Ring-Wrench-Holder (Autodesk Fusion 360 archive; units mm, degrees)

design "Ring-Wrench-Holder" references "Base"
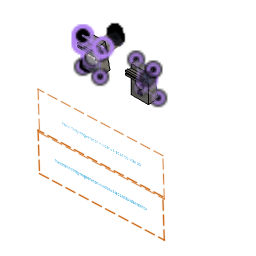
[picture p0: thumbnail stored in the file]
parameter "stick_diameter" = 24
parameter "stick_length" = 34
parameter "angle" = 10
parameter "calculated_height" = 34 (= "stick_diameter + 10 mm")
parameter "screw_tolerance" = 0.3
parameter "screw_dept" = 4
parameter "screw_hole_diameter" = 6
component_insert "Component Insert"
work_plane "WorkPlane1" AlongDistance 55.612
sketch "Sketch1" plane through (0, 55.6118, 0) normal (0, 1, 0) x axis (1, 0, 0)
  line L1 (40, -60) -> (0, -60)
sketch "Sketch2" plane through (0, 0, 0) normal (1, 0, 0) x axis (0, 1, 0)
  line L1 (65.4599, 61.7365) -> (55.6118, 60)
  line L2 (65.6118, 60) -> (55.6118, 60)
  line L3 (64.9888, 6.8204) -> (55.6118, 60)
  line L4 (74.8369, 8.5569) -> (65.4599, 61.7365)
  line L5 (64.9888, 6.8204) -> (74.8369, 8.5569)
  point P2 (55.6118, 60)
  point P3 (55.6118, 60)
  point P6 (55.6118, 60)
  point P4 (65.4599, 61.7365)
  point P7 (64.9888, 6.8204)
  horizontal L2
  coincident P2 P3
  coincident P2 P6
  perpendicular L1 L3
  perpendicular L1 L4
  equal L3 L4
  dimension "d6" distance P3 P4 = 10
  dimension "d7" angle L1 L2 = 10 (= "angle")
  dimension "d9" distance P6 P7 = 54 (= "calculated_height + 20 mm")
extrude "Extrude1" new body sketch "Sketch2" profile of L1 L3 L4 L5 along normal blind 34 (= "calculated_height") bodies "Holder"
sketch "Sketch3" plane through (0, 0, 0) normal (-1, 0, 0) x axis (0, -1, 0)
  line L1 (-55.6118, 60) -> (-64.9888, 6.8204)
  line L2 (-65.4599, 61.7365) -> (-55.6118, 60)
  line L3 (-74.8369, 8.5569) -> (-65.4599, 61.7365)
  line L4 (-64.9888, 6.8204) -> (-74.8369, 8.5569)
  line L5 (-55.6118, 6.8204) -> (-55.6118, 60)
  line L6 (-64.9888, 6.8204) -> (-55.6118, 6.8204)
  point P3 (-55.6118, 60)
  point P8 (-55.6118, 60)
  point P7 (-64.9888, 6.8204)
  point P10 (-64.9888, 6.8204)
  coincident P3 P8
  vertical L5
  coincident P7 P10
  perpendicular L5 L6
extrude "Extrude2" add sketch "Sketch3" profile of L1 L5 L6 to an object
sketch "Sketch4" plane through (0, 74.0436, 13.0559) normal (0, 0.9848, 0.1736) x axis (-1, 0, 0)
  line L1 (0, 49.4316) -> (0, -4.5684)
  line L2 (-34, 49.4316) -> (0, 49.4316)
  line L3 (-34, -4.5684) -> (-34, 49.4316)
  line L4 (0, -4.5684) -> (-34, -4.5684)
  line L5 (0, -4.5684) -> (-34, 49.4316)
  circle C1 centre (-17, 22.4316) radius 12
  point P4 (-34, 49.4316)
  point P6 (-34, 49.4316)
  point P2 (0, -4.5684)
  point P7 (0, -4.5684)
  point P8 (-17, 22.4316)
  coincident P4 P6
  coincident P2 P7
  midpoint L5 P8
  dimension "d14" diameter C1 = 24 (= "stick_diameter")
extrude "Extrude3" new body sketch "Sketch4" profile of C1 along normal blind 34 (= "stick_length") bodies "Stick"
sketch "Sketch5" plane through (0, 107.5271, 18.9599) normal (0, 0.9848, 0.1736) x axis (-1, 0, 0)
  line L1 (-17, 34.4316) -> (-17, 22.4316)
  line L2 (-22.9375, 22.1004) -> (-20.2555, 27.408)
  line L3 (-19.6819, 17.124) -> (-22.9375, 22.1004)
  line L4 (-13.7445, 17.4551) -> (-19.6819, 17.124)
  line L5 (-11.0625, 22.7627) -> (-13.7445, 17.4551)
  line L6 (-14.3181, 27.7392) -> (-11.0625, 22.7627)
  line L7 (-20.2555, 27.408) -> (-14.3181, 27.7392)
  circle C1 centre (-17, 22.4316) radius 12
  circle C2 centre (-17, 22.4316) radius 3.15
  point P2 (-17, 22.4316)
  point P3 (-17, 22.4316)
  point P4 (-17, 34.4316)
  point P11 (-17, 22.4316)
  point P12 (-17, 22.4316)
  coincident P2 P3
  coincident C1 P4
  vertical L1
  coincident P2 P11
  coincident P3 P12
  dimension "d17" distance P11 L7 = 5.15 (= "5 mm + ( screw_tolerance / 2 )")
  dimension "d23" diameter C2 = 6.3 (= "screw_hole_diameter + screw_tolerance")
extrude "Extrude4" cut sketch "Sketch5" profile of L2 L3 L4 L5 L6 L7 along a picked direction blind -4
extrude "Extrude5" cut sketch "Sketch5" profile of C2 along a picked direction blind -84 (= "-stick_length - 50 mm")
work_plane "WorkPlane2" sketch "Sketch5" AlongDistance 60
sketch "Sketch6" plane through (0, 64.1955, 11.3194) normal (0, 0.9848, 0.1736) x axis (-1, 0, 0)
  line L1 (-19.6819, 17.124) -> (-22.9375, 22.1004)
  line L2 (-13.7445, 17.4551) -> (-19.6819, 17.124)
  line L3 (-11.0625, 22.7627) -> (-13.7445, 17.4551)
  line L4 (-14.3181, 27.7392) -> (-11.0625, 22.7627)
  line L5 (-22.9375, 22.1004) -> (-20.2555, 27.408)
  line L6 (-20.2555, 27.408) -> (-14.3181, 27.7392)
  circle C1 centre (-17, 22.4316) radius 12
  circle C2 centre (-17, 22.4316) radius 5.9467
  circle C3 centre (-17, 22.4316) radius 7.9467
  point P6 (-14.3181, 27.7392)
  concentric C1 C2
  coincident P6 C2
  dimension "d45" = 2
extrude "Extrude6" cut sketch "Sketch6" profile of L1 L2 L3 L4 L5 L6 C3 against normal blind 29
extrude "Extrude7" new body of existing geometry blind 37
extrude "Extrude8" add of existing geometry to an object
extrude "Extrude9" cut of existing geometry to an object
sketch "Text" plane through (0, 55.6118, 0) normal (0, -1, 0) x axis (1, 0, 0)
  line L1 (20.1325, 31.916) -> (0, 31.916)
  curve K1
  curve K2
  curve K3
  curve K4
  line L2 (0, 47.1259) -> (34, 47.1259)
  line L3 (0, 6.8204) -> (0, 47.1259)
  line L4 (34, 6.8204) -> (0, 6.8204)
  line L5 (34, 47.1259) -> (34, 6.8204)
  closed curve K5 centre (17, 32.5835)
  point P2 (0, 31.916)
  point P7 (34, 6.8204)
  coincident P2
  equal K1 L4
  coincident P7
  coincident L4
  dimension "d35" Text1-Height = 2
sketch "Filename" plane through (0, 0, 0) normal (0, 1, 0) x axis (1, 0, 0)
  dimension "d36" = 5
  dimension "d41" = 5
  dimension "d42" = 5
extrude "Extrude10" cut sketch "Text" against normal blind 2
copy_paste_bodies "CopyPasteBodies1"
move "Move1"
sketch "Sketch9" plane through (0, 74.0436, 13.0559) normal (0, 0.9848, 0.1736) x axis (-1, 0, 0)
  line L1 (-95, 49.4316) -> (-95, -4.5684)
  line L2 (-129, 49.4316) -> (-95, 49.4316)
  line L3 (-129, -4.5684) -> (-129, 49.4316)
  line L4 (-95, -4.5684) -> (-129, -4.5684)
  line L5 (-112, -4.5684) -> (-112, 49.4316)
  line L6 (-117.9415, 22.1826) -> (-115.1864, 27.4526)
  line L7 (-114.7551, 17.1616) -> (-117.9415, 22.1826)
  line L8 (-108.8136, 17.4106) -> (-114.7551, 17.1616)
  line L9 (-106.0585, 22.6806) -> (-108.8136, 17.4106)
  line L10 (-109.2449, 27.7016) -> (-106.0585, 22.6806)
  line L11 (-115.1864, 27.4526) -> (-109.2449, 27.7016)
  circle C1 centre (-112, 22.4316) radius 3.15
  circle C2 centre (-112, 22.4316) radius 3.15
  point P8 (-112, 49.4316)
  point P9 (-112, -4.5684)
  point P2 (-112, 22.4316)
  point P16 (-112, 22.4316)
  midpoint L2 P8
  midpoint L4 P9
  coincident P2 P16
  dimension "d44" distance P16 L11 = 5.15 (= "5 mm + ( screw_tolerance / 2 )")
extrude "Extrude11" cut sketch "Sketch9" profile of C1 C2 no distance stored
combine "Combine1" bodies "Holder"
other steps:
base_feature "Base Feature" bodies "Holder", "No stick"
named bodies: "Holder", "Stick", "No stick"

design "Base"
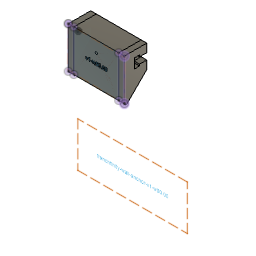
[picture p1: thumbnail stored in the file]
parameter "wall_anchor_height" = 60
parameter "wall_anchor_width" = 20
parameter "wall_anchor_angle" = 45
parameter "width_per_slot" = 40
parameter "slot_inner_width" = 8.5
parameter "slot_inner_height" = 4.5
parameter "slot_outer_width" = 5.6
parameter "slot_outer_height" = 6.5
parameter "slot_dept" = 15
parameter "print_tolerance" = 0.12
parameter "base_plate_thickness" = 16
parameter "base_plate_slot_height" = 50
parameter "wall_anchor_angle_rounded_border" = 1.5
parameter "base_plate_screw_hole_diameter" = 4
parameter "base_plate_screw_head_diameter" = 8
parameter "base_plate_screw_head_height" = 4
parameter "base_plate_screw_hole_side_distance" = 7
parameter "slot_screw_head_width" = 4.42 (= "4.3 mm + print_tolerance")
parameter "slot_screw_thread_width" = 2.12 (= "2 mm + print_tolerance")
parameter "slot_screw_head_height" = 2.12 (= "2 mm + print_tolerance")
parameter "width" = 50
parameter "filament_hole_width" = 1.7
sketch "Side" plane through (0, 0, 0) normal (1, 0, 0) x axis (0, 1, 0)
  line L1 (39.6118, 0) -> (19.6118, 0)
  line L2 (39.6118, 60) -> (39.6118, 0)
  line L3 (19.6118, 60) -> (39.6118, 60)
  line L4 (19.6118, 0) -> (19.6118, 60)
  line L5 (39.6118, 39.6118) -> (0, 0)
  line L6 (56.0196, 0) -> (0, 0)
  point P1 (0, 0)
  point P6 (0, 0)
  point P7 (39.6118, 39.6118)
  point P2 (19.6118, 0)
  point P3 (39.6118, 0)
  point P5 (19.6118, 60)
  horizontal L1
  vertical L2
  horizontal L3
  vertical L4
  horizontal L6
  coincident P1 P6
  coincident L2 P7
  dimension "d4" distance P2 P3 = 20 (= "wall_anchor_width")
  dimension "d5" distance P2 P5 = 60 (= "wall_anchor_height")
  dimension "d6" angle L5 L6 = 45 (= "wall_anchor_angle")
extrude "Extrude1" new body sketch "Side" profile of L1 L2 L3 L4 L5 along normal blind 40 (= "width_per_slot")
sketch "Slot LeftToRight" plane through (0, 0, 0) normal (-1, 0, 0) x axis (0, -1, 0)
  line L1 (-19.6118, 60) -> (-19.6118, 19.6118)
  line L2 (-39.6118, 60) -> (-19.6118, 60)
  line L3 (-39.6118, 39.6118) -> (-39.6118, 60)
  line L4 (-19.6118, 19.6118) -> (-39.6118, 39.6118)
  line L5 (-39.6118, 52.6059) -> (-39.6118, 49.8059)
  line L6 (-39.6118, 47.0059) -> (-39.6118, 49.8059)
  line L7 (-33.1118, 52.6059) -> (-39.6118, 52.6059)
  line L8 (-28.6118, 49.8059) -> (-39.6118, 49.8059)
  line L9 (-28.6118, 54.0559) -> (-28.6118, 49.8059)
  line L10 (-33.1118, 54.0559) -> (-28.6118, 54.0559)
  line L11 (-33.1118, 52.6059) -> (-33.1118, 54.0559)
  line L12 (-28.6118, 45.5559) -> (-28.6118, 49.8059)
  line L13 (-33.1118, 45.5559) -> (-28.6118, 45.5559)
  line L14 (-33.1118, 47.0059) -> (-33.1118, 45.5559)
  line L15 (-33.1118, 47.0059) -> (-39.6118, 47.0059)
  point P6 (-39.6118, 49.8059)
  point P7 (-39.6118, 52.6059)
  point P17 (-39.6118, 47.0059)
  point P9 (-33.1118, 52.6059)
  point P16 (-33.1118, 47.0059)
  point P10 (-28.6118, 49.8059)
  point P13 (-28.6118, 49.8059)
  point P11 (-28.6118, 54.0559)
  point P14 (-28.6118, 45.5559)
  point P12 (-33.1118, 54.0559)
  point P15 (-33.1118, 45.5559)
  midpoint L3 P6
  parallel L3 L5
  parallel L3 L6
  perpendicular L3 L7
  perpendicular L6 L8
  perpendicular L8 L9
  perpendicular L9 L10
  symmetric P7 L8 P17
  symmetric P9 L8 P16
  symmetric P10 L8 P13
  symmetric L8 P11 P14
  symmetric L8 P12 P15
  dimension "d80" distance P6 P7 = 2.8 (= "slot_outer_width / 2")
  dimension "d82" distance P7 P9 = 6.5 (= "slot_outer_height")
  dimension "d84" distance P6 P10 = 11 (= "slot_outer_height + slot_inner_height")
  dimension "d85" distance P10 P11 = 4.25 (= "slot_inner_width / 2")
  dimension "d86" distance P11 P12 = 4.5 (= "slot_inner_height")
extrude "Extrude3" cut sketch "Slot LeftToRight" profile of L3 L5 L6 L7 L9 L10 L11 L12 L13 L14 L15 against normal blind 40 (magnitude of "width_per_slot * -1")
sketch "Plate" plane through (0, 39.6118, 0) normal (0, 1, 0) x axis (-1, 0, 0)
  line L1 (0, 39.6118) -> (-40, 39.6118)
  line L2 (-40, 60) -> (0, 60)
  line L3 (0, 10) -> (0, 60)
  line L4 (-40, 10) -> (-40, 60)
  line L5 (-40, 10) -> (0, 10)
  line L6 (-40, 47.0059) -> (0, 47.0059)
  line L7 (-40, 52.6059) -> (-40, 60)
  line L8 (0, 60) -> (0, 52.6059)
  line L9 (0, 52.6059) -> (-40, 52.6059)
  line L10 (-40, 60) -> (0, 60)
  line L11 (-40, 39.6118) -> (-40, 47.0059)
  line L12 (0, 47.0059) -> (0, 39.6118)
  point P2 (0, 60)
  point P3 (-40, 60)
  point P4 (0, 10)
  point P5 (-40, 10)
  perpendicular L1 L3
  perpendicular L1 L4
  dimension "d36" distance P2 P3 = 40 (= "width_per_slot")
  dimension "d37" distance P2 P4 = 50 (= "base_plate_slot_height")
  dimension "d39" distance P3 P5 = 50 (= "base_plate_slot_height")
extrude "Extrude6" new body sketch "Plate" profile of L1 L2 L3 L4 L5 L6 L7 L8 L9 L10 along normal blind 16 (= "base_plate_thickness") bodies "Base plate with slot"
sketch "Slot" plane through (0, 0, 0) normal (-1, 0, 0) x axis (0, -1, 0)
  line L1 (-19.6118, 60) -> (-19.6118, 19.6118)
  line L2 (-39.6118, 60) -> (-19.6118, 60)
  line L3 (-39.6118, 52.6059) -> (-39.6118, 60)
  line L4 (-33.1118, 52.6059) -> (-39.6118, 52.6059)
  line L5 (-33.1118, 54.0559) -> (-33.1118, 52.6059)
  line L6 (-28.6118, 54.0559) -> (-33.1118, 54.0559)
  line L7 (-28.6118, 45.5559) -> (-28.6118, 54.0559)
  line L8 (-33.1118, 45.5559) -> (-28.6118, 45.5559)
  line L9 (-33.1118, 47.0059) -> (-33.1118, 45.5559)
  line L10 (-39.6118, 47.0059) -> (-33.1118, 47.0059)
  line L11 (-39.6118, 39.6118) -> (-39.6118, 47.0059)
  line L12 (-19.6118, 19.6118) -> (-39.6118, 39.6118)
  line L13 (-33.1118, 52.6059) -> (-39.6118, 52.6059)
  line L14 (-33.1118, 54.0559) -> (-33.1118, 52.6059)
  line L15 (-28.6118, 54.0559) -> (-33.1118, 54.0559)
  line L16 (-28.6118, 45.5559) -> (-28.6118, 54.0559)
  line L17 (-33.1118, 45.5559) -> (-28.6118, 45.5559)
  line L18 (-33.1118, 47.0059) -> (-33.1118, 45.5559)
  line L19 (-39.6118, 47.0059) -> (-33.1118, 47.0059)
  line L20 (-39.6118, 10) -> (-39.6118, 60)
  line L21 (-32.9918, 52.4859) -> (-39.6118, 52.4859)
  line L22 (-32.9918, 53.9359) -> (-32.9918, 52.4859)
  line L23 (-28.7318, 53.9359) -> (-32.9918, 53.9359)
  line L24 (-28.7318, 45.6759) -> (-28.7318, 53.9359)
  line L25 (-32.9918, 45.6759) -> (-28.7318, 45.6759)
  line L26 (-32.9918, 47.1259) -> (-32.9918, 45.6759)
  line L27 (-39.6118, 47.1259) -> (-32.9918, 47.1259)
  line L28 (-33.1118, 52.6059) -> (-39.6118, 52.6059)
  line L29 (-33.1118, 52.6059) -> (-33.1118, 54.0559)
  line L30 (-28.6118, 54.0559) -> (-33.1118, 54.0559)
  line L31 (-28.6118, 45.5559) -> (-28.6118, 54.0559)
  line L32 (-33.1118, 45.5559) -> (-28.6118, 45.5559)
  line L33 (-33.1118, 47.0059) -> (-33.1118, 45.5559)
  line L34 (-39.6118, 47.0059) -> (-33.1118, 47.0059)
  line L35 (-39.6118, 47.0059) -> (-39.6118, 52.6059)
  line L36 (-49.1118, 52.6059) -> (-55.6118, 52.6059)
  line L37 (-49.1118, 52.6059) -> (-49.1118, 54.0559)
  line L38 (-44.6118, 54.0559) -> (-49.1118, 54.0559)
  line L39 (-44.6118, 45.5559) -> (-44.6118, 54.0559)
  line L40 (-49.1118, 45.5559) -> (-44.6118, 45.5559)
  line L41 (-49.1118, 47.0059) -> (-49.1118, 45.5559)
  line L42 (-55.6118, 47.0059) -> (-49.1118, 47.0059)
  line L43 (-55.6118, 47.0059) -> (-55.6118, 52.6059)
  point P15 (-39.6118, 52.6059)
  point P33 (-39.6118, 52.6059)
  point P16 (-33.1118, 52.6059)
  point P34 (-33.1118, 52.6059)
  point P17 (-33.1118, 54.0559)
  point P35 (-33.1118, 54.0559)
  point P36 (-33.1118, 52.6059)
  point P18 (-28.6118, 54.0559)
  point P37 (-28.6118, 54.0559)
  point P19 (-28.6118, 45.5559)
  point P38 (-28.6118, 45.5559)
  point P10 (-28.6118, 45.5559)
  point P39 (-28.6118, 45.5559)
  point P11 (-33.1118, 45.5559)
  point P40 (-33.1118, 45.5559)
  point P41 (-33.1118, 45.5559)
  point P12 (-33.1118, 47.0059)
  point P42 (-33.1118, 47.0059)
  point P21 (-33.1118, 47.0059)
  point P43 (-33.1118, 47.0059)
  point P22 (-39.6118, 47.0059)
  point P44 (-39.6118, 47.0059)
  point P45 (-39.6118, 52.6059)
  point P46 (-39.6118, 47.0059)
  coincident P15 P33
  coincident P16 P34
  coincident P17 P35
  coincident P16 P36
  coincident P18 P37
  coincident P19 P38
  coincident P10 P39
  coincident P11 P40
  coincident P11 P41
  coincident P12 P42
  coincident P21 P43
  coincident P22 P44
  coincident P15 P45
  coincident P22 P46
  dimension "d91" = 0.12 (= "print_tolerance")
  dimension "d96" R-Pattern1-uDistance = -16 (= "base_plate_thickness * -1")
  dimension "d97" R-Pattern1-vDistance = 0
extrude "Extrude7" add sketch "Slot" profile of L20 L24 L23 L27 L22 L25 L26 L21 against normal blind 40 (magnitude of "width_per_slot * -1")
extrude "Extrude8" cut sketch "Slot" profile of L36 L37 L38 L39 L40 L41 L42 L43 no distance stored
sketch "Sketch3" plane through (0, 0, 0) normal (-1, 0, 0) x axis (0, -1, 0)
  line L1 (-32.9918, 47.1259) -> (-39.6118, 47.1259)
  line L2 (-32.9918, 45.6759) -> (-32.9918, 47.1259)
  line L3 (-28.7318, 45.6759) -> (-32.9918, 45.6759)
  line L4 (-28.7318, 53.9359) -> (-28.7318, 45.6759)
  line L5 (-32.9918, 53.9359) -> (-28.7318, 53.9359)
  line L6 (-32.9918, 52.4859) -> (-32.9918, 53.9359)
  line L7 (-39.6118, 52.4859) -> (-32.9918, 52.4859)
  line L8 (-44.6118, 45.5559) -> (-44.6118, 54.0559)
  line L9 (-32.9918, 52.4859) -> (-39.6118, 52.4859)
  line L10 (-32.9918, 53.9359) -> (-32.9918, 52.4859)
  line L11 (-28.7318, 53.9359) -> (-32.9918, 53.9359)
  line L12 (-28.7318, 45.6759) -> (-28.7318, 53.9359)
  line L13 (-32.9918, 45.6759) -> (-28.7318, 45.6759)
  line L14 (-32.9918, 47.1259) -> (-32.9918, 45.6759)
  line L15 (-39.6118, 47.1259) -> (-32.9918, 47.1259)
  line L16 (-39.6118, 47.1259) -> (-39.6118, 52.4859)
  line L17 (-55.6118, 52.4859) -> (-48.9918, 52.4859)
  line L18 (-48.9918, 52.4859) -> (-48.9918, 53.9359)
  line L19 (-48.9918, 53.9359) -> (-44.7318, 53.9359)
  line L20 (-44.7318, 45.6759) -> (-44.7318, 53.9359)
  line L21 (-48.9918, 45.6759) -> (-44.7318, 45.6759)
  line L22 (-48.9918, 47.1259) -> (-48.9918, 45.6759)
  line L23 (-55.6118, 47.1259) -> (-48.9918, 47.1259)
  line L24 (-55.6118, 47.1259) -> (-55.6118, 52.4859)
  line L25 (-55.6118, 47.0059) -> (-49.1118, 47.0059)
  line L26 (-55.6118, 10) -> (-55.6118, 47.0059)
  line L27 (-39.6118, 10) -> (-55.6118, 10)
  line L28 (-39.6118, 47.1259) -> (-39.6118, 10)
  line L29 (-39.6118, 60) -> (-39.6118, 52.4859)
  line L30 (-55.6118, 60) -> (-39.6118, 60)
  line L31 (-55.6118, 52.6059) -> (-55.6118, 60)
  line L32 (-49.1118, 52.6059) -> (-55.6118, 52.6059)
  line L33 (-49.1118, 54.0559) -> (-49.1118, 52.6059)
  line L34 (-44.6118, 54.0559) -> (-49.1118, 54.0559)
  line L35 (-49.1118, 45.5559) -> (-44.6118, 45.5559)
  line L36 (-49.1118, 47.0059) -> (-49.1118, 45.5559)
  point P9 (-39.6118, 52.4859)
  point P20 (-39.6118, 52.4859)
  point P19 (-39.6118, 47.1259)
  point P21 (-39.6118, 47.1259)
  coincident P9 P20
  coincident P19 P21
  dimension "d105" R-Pattern1-vDistance = 0
extrude "Extrude3" new body sketch "Sketch3" profile of L17 L18 L19 L20 L21 L22 L23 L24 against normal blind 40 (magnitude of "width_per_slot * -1")
sketch "Screw hole" plane through (0, 28.6118, 0) normal (0, 1, 0) x axis (-1, 0, 0)
  line L1 (0, 54.0559) -> (0, 45.5559)
  line L2 (-40, 54.0559) -> (0, 54.0559)
  line L3 (-40, 45.5559) -> (-40, 54.0559)
  line L4 (0, 45.5559) -> (-40, 45.5559)
  line L5 (0, 45.5559) -> (-40, 54.0559)
  line L6 (-40, 45.5559) -> (0, 54.0559)
  circle C1 centre (-20, 49.8059) radius 2.21
  circle C2 centre (-20, 49.8059) radius 1.06
  point P4 (-40, 54.0559)
  point P6 (-40, 54.0559)
  point P2 (0, 45.5559)
  point P7 (0, 45.5559)
  point P3 (0, 54.0559)
  point P8 (0, 54.0559)
  point P5 (-40, 45.5559)
  point P9 (-40, 45.5559)
  point P10 (-20, 49.8059)
  coincident P4 P6
  coincident P2 P7
  coincident P3 P8
  coincident P5 P9
  midpoint L5 P10
  concentric C1 C2
  dimension "d119" diameter C1 = 4.42 (= "slot_screw_head_width")
  dimension "d120" diameter C2 = 2.12 (= "slot_screw_thread_width")
extrude "Extrude4" cut sketch "Screw hole" profile of C2 against normal blind 2000
extrude "Extrude5" cut sketch "Screw hole" profile of C1 C2 no distance stored
fillet "Fillet1" radius 1.5 (= "wall_anchor_angle_rounded_border")
work_plane "WorkPlane1" sketch "Slot LeftToRight" AlongDistance -20 (= "-width_per_slot / 2")
sketch "Screw head" plane through (20, 0, 0) normal (-1, 0, 0) x axis (0, -1, 0)
  line L1 (-28.6118, 52.0159) -> (-28.6118, 47.5959)
  line L2 (-26.4918, 52.0159) -> (-26.4918, 47.5959)
  line L3 (-26.4918, 48.7459) -> (-26.4918, 50.8659)
  line L4 (-26.4918, 50.8659) -> (-28.6118, 52.0159)
  line L5 (-26.4918, 52.0159) -> (-28.6118, 52.0159)
  point P3 (-28.6118, 52.0159)
  point P8 (-28.6118, 52.0159)
  point P6 (-26.4918, 50.8659)
  point P9 (-26.4918, 50.8659)
  point P10 (-28.6118, 52.0159)
  point P5 (-26.4918, 52.0159)
  point P11 (-26.4918, 52.0159)
  coincident P3 P8
  coincident P6 P9
  coincident P3 P10
  coincident P5 P11
revolve "Revolve1" sketch "Screw head" AlongAngle 360
sketch "Plate" plane through (0, 39.6118, 0) normal (0, 1, 0) x axis (-1, 0, 0)
  line L1 (0, 39.6118) -> (-40, 39.6118)
  line L2 (-40, 60) -> (0, 60)
  line L3 (0, 10) -> (0, 60)
  line L4 (-40, 10) -> (-40, 60)
  line L5 (-40, 10) -> (0, 10)
  line L6 (-40, 47.0059) -> (0, 47.0059)
  line L7 (-40, 39.6118) -> (-40, 47.0059)
  line L8 (0, 47.0059) -> (0, 39.6118)
  line L9 (0, 52.6059) -> (-40, 52.6059)
  line L10 (-40, 60) -> (0, 60)
  line L11 (0, 60) -> (0, 52.6059)
  line L12 (-40, 52.6059) -> (-40, 60)
  point P2 (0, 60)
  point P3 (-40, 60)
  point P4 (0, 10)
  point P5 (-40, 10)
  perpendicular L1 L3
  perpendicular L1 L4
  dimension "d36_1" distance P2 P3 = 40 (= "width_per_slot")
  dimension "d37_1" distance P2 P4 = 50 (= "base_plate_slot_height")
  dimension "d39_1" distance P3 P5 = 50 (= "base_plate_slot_height")
extrude "Extrude6" new body sketch "Plate" profile of L1 L2 L3 L4 L5 L6 L7 L8 L9 L10 along normal blind 16 (= "base_plate_thickness") named "d89_1" bodies "Base plate with slot"
sketch "Slot" plane through (0, 0, 0) normal (-1, 0, 0) x axis (0, -1, 0)
  line L1 (-19.6118, 60) -> (-19.6118, 23.2332)
  line L2 (-39.6118, 60) -> (-19.6118, 60)
  line L3 (-39.6118, 52.6059) -> (-39.6118, 60)
  line L4 (-33.1118, 52.6059) -> (-39.6118, 52.6059)
  line L5 (-33.1118, 54.0559) -> (-33.1118, 52.6059)
  line L6 (-28.6118, 54.0559) -> (-33.1118, 54.0559)
  line L7 (-28.6118, 45.5559) -> (-28.6118, 54.0559)
  line L8 (-33.1118, 45.5559) -> (-28.6118, 45.5559)
  line L9 (-33.1118, 47.0059) -> (-33.1118, 45.5559)
  line L10 (-39.6118, 47.0059) -> (-33.1118, 47.0059)
  line L11 (-39.6118, 39.6118) -> (-39.6118, 47.0059)
  line L12 (-22.1725, 22.1725) -> (-39.6118, 39.6118)
  line L13 (-33.1118, 52.6059) -> (-39.6118, 52.6059)
  line L14 (-33.1118, 54.0559) -> (-33.1118, 52.6059)
  line L15 (-28.6118, 54.0559) -> (-33.1118, 54.0559)
  line L16 (-28.6118, 45.5559) -> (-28.6118, 54.0559)
  line L17 (-33.1118, 45.5559) -> (-28.6118, 45.5559)
  line L18 (-33.1118, 47.0059) -> (-33.1118, 45.5559)
  line L19 (-39.6118, 47.0059) -> (-33.1118, 47.0059)
  line L20 (-39.6118, 10) -> (-39.6118, 60)
  line L21 (-32.9918, 52.4859) -> (-39.6118, 52.4859)
  line L22 (-32.9918, 53.9359) -> (-32.9918, 52.4859)
  line L23 (-28.7318, 53.9359) -> (-32.9918, 53.9359)
  line L24 (-28.7318, 45.6759) -> (-28.7318, 53.9359)
  line L25 (-32.9918, 45.6759) -> (-28.7318, 45.6759)
  line L26 (-32.9918, 47.1259) -> (-32.9918, 45.6759)
  line L27 (-39.6118, 47.1259) -> (-32.9918, 47.1259)
  line L28 (-33.1118, 52.6059) -> (-39.6118, 52.6059)
  line L29 (-33.1118, 52.6059) -> (-33.1118, 54.0559)
  line L30 (-28.6118, 54.0559) -> (-33.1118, 54.0559)
  line L31 (-28.6118, 45.5559) -> (-28.6118, 54.0559)
  line L32 (-33.1118, 45.5559) -> (-28.6118, 45.5559)
  line L33 (-33.1118, 47.0059) -> (-33.1118, 45.5559)
  line L34 (-39.6118, 47.0059) -> (-33.1118, 47.0059)
  line L35 (-39.6118, 47.0059) -> (-39.6118, 52.6059)
  line L36 (-49.1118, 52.6059) -> (-55.6118, 52.6059)
  line L37 (-49.1118, 52.6059) -> (-49.1118, 54.0559)
  line L38 (-44.6118, 54.0559) -> (-49.1118, 54.0559)
  line L39 (-44.6118, 45.5559) -> (-44.6118, 54.0559)
  line L40 (-49.1118, 45.5559) -> (-44.6118, 45.5559)
  line L41 (-49.1118, 47.0059) -> (-49.1118, 45.5559)
  line L42 (-55.6118, 47.0059) -> (-49.1118, 47.0059)
  line L43 (-55.6118, 47.0059) -> (-55.6118, 52.6059)
  arc A1 centre (-21.1118, 23.2332) radius 1.5 clockwise from (-19.6118, 23.2332) to (-22.1725, 22.1725)
  point P15 (-39.6118, 52.6059)
  point P33 (-39.6118, 52.6059)
  point P16 (-33.1118, 52.6059)
  point P34 (-33.1118, 52.6059)
  point P17 (-33.1118, 54.0559)
  point P35 (-33.1118, 54.0559)
  point P36 (-33.1118, 52.6059)
  point P18 (-28.6118, 54.0559)
  point P37 (-28.6118, 54.0559)
  point P19 (-28.6118, 45.5559)
  point P38 (-28.6118, 45.5559)
  point P10 (-28.6118, 45.5559)
  point P39 (-28.6118, 45.5559)
  point P11 (-33.1118, 45.5559)
  point P40 (-33.1118, 45.5559)
  point P41 (-33.1118, 45.5559)
  point P12 (-33.1118, 47.0059)
  point P42 (-33.1118, 47.0059)
  point P21 (-33.1118, 47.0059)
  point P43 (-33.1118, 47.0059)
  point P22 (-39.6118, 47.0059)
  point P44 (-39.6118, 47.0059)
  point P45 (-39.6118, 52.6059)
  point P46 (-39.6118, 47.0059)
  coincident P15 P33
  coincident P16 P34
  coincident P17 P35
  coincident P16 P36
  coincident P18 P37
  coincident P19 P38
  coincident P10 P39
  coincident P11 P40
  coincident P11 P41
  coincident P12 P42
  coincident P21 P43
  coincident P22 P44
  coincident P15 P45
  coincident P22 P46
  dimension "d91_1" = 0.12 (= "print_tolerance")
  dimension "d96_1" R-Pattern1-uDistance = -16 (= "base_plate_thickness * -1")
  dimension "d97_1" R-Pattern1-vDistance = 0
extrude "Extrude8" cut sketch "Slot" profile of L36 L37 L38 L39 L40 L41 L42 L43 no distance stored
sketch "Screw" plane through (0, 55.6118, 0) normal (0, 1, 0) x axis (-1, 0, 0)
  line L1 (-40, 47.0059) -> (0, 47.0059)
  line L2 (-40, 10) -> (-40, 47.0059)
  line L3 (0, 10) -> (-40, 10)
  line L4 (0, 47.0059) -> (0, 10)
  line L5 (-33, 17) -> (-33, 40.0059)
  line L6 (-7, 17) -> (-33, 17)
  line L7 (-7, 40.0059) -> (-7, 17)
  line L8 (-33, 40.0059) -> (-7, 40.0059)
  circle C1 centre (-33, 17) radius 4
  circle C2 centre (-33, 17) radius 2
  point P7 (-33, 17)
  point P10 (-33, 17)
  coincident P7 P10
  concentric C1 C2
  dimension "d127" = -7 (= "base_plate_screw_hole_side_distance * -1")
  dimension "d128" diameter C1 = 8
  dimension "d129" diameter C2 = 4
rectangular_pattern "R-Pattern2" countU 1 (= "floor(( width / mm ) / ( width_per_slot / cm * 10 ))") uSpaceDistance 40 (= "width_per_slot") vSpaceDistance 0
work_plane "WorkPlane2"
extrude "Extrude12" new body of existing geometry no distance stored
mirror "Mirror3" mirrorStitchTolerance 0.1
sketch "filename" plane through (0, 19.6118, 0) normal (0, -1, 0) x axis (1, 0, 0)
  dimension "d216" = 3
sketch "Sketch14" plane through (0, 19.6118, 0) normal (0, -1, 0) x axis (1, 0, 0)
  line L1 (45, 60) -> (45, 23.2332)
  line L2 (40, 23.2332) -> (40, 60)
  line L3 (45, 23.2332) -> (40, 23.2332)
  line L4 (45, 60) -> (45, 23.2332)
  line L5 (40, 60) -> (45, 60)
  line L6 (0, 60) -> (0, 23.2332)
  line L7 (-5, 60) -> (0, 60)
  line L8 (-5, 23.2332) -> (-5, 60)
  line L9 (0, 23.2332) -> (-5, 23.2332)
  curve K1
  curve K2
  curve K3
  curve K4
  point P4 (45, 23.2332)
  point P2 (-5, 60)
  coincident P4
  coincident P2
  dimension "d229" Text1-Height = 3
extrude "Extrude19" cut sketch "Sketch14" against normal blind 2
extrude "Extrude14" cut of existing geometry blind 5 (= "( width_per_slot - width ) / -2")
extrude "Extrude15" cut of existing geometry blind 5 (= "( width_per_slot - width ) / -2")
extrude "Extrude9" cut of existing geometry blind -39 (= "-width_per_slot + 1 mm")
extrude "Extrude10" add of existing geometry blind 49 (= "width - 1 mm")
sketch "Sketch7" plane through (0, 39.6118, 0) normal (0, -1, 0) x axis (1, 0, 0)
  dimension "d236" = 3
extrude "Extrude11" cut sketch "Sketch7" against normal blind 2
sketch "File name" plane through (0, 39.6118, 0) normal (0, -1, 0) x axis (1, 0, 0)
  line L1 (19.0624, 30.0752) -> (18.825, 30.0752)
  line L2 (19.0624, 27.063) -> (19.0624, 30.0752)
  line L3 (18.6941, 27.063) -> (19.0624, 27.063)
  line L4 (18.6941, 29.4102) -> (18.6941, 27.063)
  curve K1 (18.3441, 29.1564) -> (18.6941, 29.4102)
  curve K2 (17.9574, 28.9661) -> (18.3441, 29.1564)
  line L5 (17.9574, 29.3222) -> (17.9574, 28.9661)
  curve K3 (18.4976, 29.6741) -> (17.9574, 29.3222)
  curve K4 (18.825, 30.0752) -> (18.4976, 29.6741)
  line L6 (22.2896, 27.063) -> (22.7295, 28.7349)
  line L7 (21.9048, 27.063) -> (22.2896, 27.063)
  line L8 (21.2398, 29.2362) -> (21.9048, 27.063)
  line L9 (21.6204, 29.2362) -> (21.2398, 29.2362)
  line L10 (21.9662, 27.9818) -> (21.6204, 29.2362)
  line L11 (22.0952, 27.5152) -> (21.9662, 27.9818)
  curve K5 (22.2077, 27.9634) -> (22.0952, 27.5152)
  line L12 (22.5535, 29.2362) -> (22.2077, 27.9634)
  line L13 (22.9321, 29.2362) -> (22.5535, 29.2362)
  line L14 (23.2575, 27.9756) -> (22.9321, 29.2362)
  line L15 (23.366, 27.5602) -> (23.2575, 27.9756)
  line L16 (23.4908, 27.9797) -> (23.366, 27.5602)
  line L17 (23.8632, 29.2362) -> (23.4908, 27.9797)
  line L18 (24.2214, 29.2362) -> (23.8632, 29.2362)
  line L19 (23.542, 27.063) -> (24.2214, 29.2362)
  line L20 (23.1593, 27.063) -> (23.542, 27.063)
  line L21 (22.8134, 28.3645) -> (23.1593, 27.063)
  line L22 (22.7295, 28.7349) -> (22.8134, 28.3645)
  line L23 (21.0965, 27.9634) -> (21.0965, 28.3338)
  line L24 (19.9649, 27.9634) -> (21.0965, 27.9634)
  line L25 (19.9649, 28.3338) -> (19.9649, 27.9634)
  line L26 (21.0965, 28.3338) -> (19.9649, 28.3338)
  line L27 (16.6293, 27.063) -> (17.4519, 29.2362)
  line L28 (16.2855, 27.063) -> (16.6293, 27.063)
  line L29 (15.4587, 29.2362) -> (16.2855, 27.063)
  line L30 (15.8475, 29.2362) -> (15.4587, 29.2362)
  line L31 (16.3141, 27.9347) -> (15.8475, 29.2362)
  curve K6 (16.4533, 27.4968) -> (16.3141, 27.9347)
  curve K7 (16.5904, 27.9102) -> (16.4533, 27.4968)
  line L32 (17.0733, 29.2362) -> (16.5904, 27.9102)
  line L33 (17.4519, 29.2362) -> (17.0733, 29.2362)
  line L34 (0, 47.1259) -> (50, 47.1259)
  line L35 (0, 10) -> (0, 47.1259)
  line L36 (50, 10) -> (0, 10)
  line L37 (50, 47.1259) -> (50, 10)
  curve K8
  curve K9
  curve K10
  curve K11
  curve K12 (25.484, 29.052) -> (24.9171, 28.8638)
  curve K13 (25.3919, 27.3147) -> (25.0133, 27.4559)
  curve K14 (25.8421, 27.5152) -> (25.3919, 27.3147)
  curve K15 (25.8482, 28.5445) -> (26.0263, 28.0473)
  curve K16 (25.3857, 28.7267) -> (25.8482, 28.5445)
  curve K17 (25.0133, 27.4559) -> (24.8148, 27.8815)
  curve K18 (26.0263, 28.0473) -> (25.8421, 27.5152)
  curve K19 (25.0645, 28.6448) -> (25.3857, 28.7267)
  curve K20 (24.8394, 28.4361) -> (25.0645, 28.6448)
  curve K21 (26.4171, 28.08) -> (26.147, 28.7799)
  curve K22 (26.1797, 27.3761) -> (26.4171, 28.08)
  line L38 (24.8148, 27.8815) -> (24.428, 27.8488)
  curve K23 (26.147, 28.7799) -> (25.484, 29.052)
  curve K24 (24.7227, 27.241) -> (25.3919, 27.0118)
  curve K25 (24.428, 27.8488) -> (24.7227, 27.241)
  line L39 (24.4935, 28.4811) -> (24.8394, 28.4361)
  line L40 (24.7841, 30.022) -> (24.4935, 28.4811)
  line L41 (26.2759, 30.022) -> (24.7841, 30.022)
  line L42 (26.2759, 29.6701) -> (26.2759, 30.022)
  line L43 (25.0788, 29.6701) -> (26.2759, 29.6701)
  line L44 (24.9171, 28.8638) -> (25.0788, 29.6701)
  curve K26 (25.3919, 27.0118) -> (26.1797, 27.3761)
  curve K27 (33.9867, 29.977) -> (33.5631, 30.0752)
  curve K28 (34.2875, 29.6967) -> (33.9867, 29.977)
  curve K29 (32.6934, 29.3979) -> (32.5849, 28.5425)
  curve K30 (33.0188, 29.8992) -> (32.6934, 29.3979)
  curve K31 (33.5631, 30.0752) -> (33.0188, 29.8992)
  curve K32 (34.4737, 29.2505) -> (34.2875, 29.6967)
  curve K33 (31.9567, 29.6967) -> (31.6559, 29.977)
  curve K34 (32.1429, 29.2505) -> (31.9567, 29.6967)
  curve K35 (30.3626, 29.3979) -> (30.2541, 28.5425)
  curve K36 (30.6879, 29.8992) -> (30.3626, 29.3979)
  curve K37 (31.2323, 30.0752) -> (30.6879, 29.8992)
  curve K38 (31.6559, 29.977) -> (31.2323, 30.0752)
  curve K39 (32.8817, 27.3228) -> (33.5631, 27.0118)
  curve K40 (32.5849, 28.5425) -> (32.8817, 27.3228)
  curve K41 (34.5413, 28.5425) -> (34.4737, 29.2505)
  curve K42 (34.4328, 27.6892) -> (34.5413, 28.5425)
  curve K43 (34.1074, 27.1878) -> (34.4328, 27.6892)
  curve K44 (33.5631, 27.0118) -> (34.1074, 27.1878)
  curve K45 (27.0556, 27.3228) -> (27.737, 27.0118)
  curve K46 (26.7589, 28.5425) -> (27.0556, 27.3228)
  curve K47 (26.8673, 29.3979) -> (26.7589, 28.5425)
  curve K48 (27.1927, 29.8992) -> (26.8673, 29.3979)
  curve K49 (27.737, 30.0752) -> (27.1927, 29.8992)
  curve K50 (28.1606, 29.977) -> (27.737, 30.0752)
  curve K51 (28.4615, 29.6967) -> (28.1606, 29.977)
  curve K52 (28.6477, 29.2505) -> (28.4615, 29.6967)
  curve K53 (28.7152, 28.5425) -> (28.6477, 29.2505)
  curve K54 (28.6068, 27.6892) -> (28.7152, 28.5425)
  curve K55 (28.2814, 27.1878) -> (28.6068, 27.6892)
  curve K56 (27.737, 27.0118) -> (28.2814, 27.1878)
  curve K57 (30.5508, 27.3228) -> (31.2323, 27.0118)
  curve K58 (30.2541, 28.5425) -> (30.5508, 27.3228)
  curve K59 (32.2104, 28.5425) -> (32.1429, 29.2505)
  curve K60 (32.102, 27.6892) -> (32.2104, 28.5425)
  curve K61 (31.7766, 27.1878) -> (32.102, 27.6892)
  curve K62 (31.2323, 27.0118) -> (31.7766, 27.1878)
  line L45 (29.7159, 27.063) -> (29.7159, 27.4825)
  line L46 (29.2964, 27.063) -> (29.7159, 27.063)
  line L47 (29.2964, 27.4825) -> (29.2964, 27.063)
  line L48 (29.7159, 27.4825) -> (29.2964, 27.4825)
  dimension "d239" Text1-Height = 3
sketch "Sketch4" plane through (40, 0, 0) normal (1, 0, 0) x axis (0, 1, 0)
  line L1 (44.7318, 53.9359) -> (48.9918, 53.9359)
  line L2 (44.7318, 45.6759) -> (44.7318, 53.9359)
  line L3 (48.9918, 45.6759) -> (44.7318, 45.6759)
  line L4 (48.9918, 47.1259) -> (48.9918, 45.6759)
  line L5 (55.6118, 47.1259) -> (48.9918, 47.1259)
  line L6 (55.6118, 52.4859) -> (55.6118, 47.1259)
  line L7 (48.9918, 52.4859) -> (55.6118, 52.4859)
  line L8 (48.9918, 53.9359) -> (48.9918, 52.4859)
  circle C1 centre (44.7318, 49.8059) radius 0.85
  point P10 (44.7318, 49.8059)
  midpoint L2 P10
  dimension "d241" diameter C1 = 1.7 (= "filament_hole_width")
extrude "Extrude4" cut sketch "Sketch4" profile of L2 C1 no distance stored
sketch "Sketch15" plane through (-5, 0, 0) normal (-1, 0, 0) x axis (0, -1, 0)
  line L1 (-19.6118, 60) -> (-19.6118, 23.2332)
  line L2 (-39.6118, 60) -> (-19.6118, 60)
  line L3 (-39.6118, 52.6059) -> (-39.6118, 60)
  line L4 (-33.1118, 52.6059) -> (-39.6118, 52.6059)
  line L5 (-33.1118, 54.0559) -> (-33.1118, 52.6059)
  line L6 (-28.6118, 54.0559) -> (-33.1118, 54.0559)
  line L7 (-28.6118, 45.5559) -> (-28.6118, 54.0559)
  line L8 (-33.1118, 45.5559) -> (-28.6118, 45.5559)
  line L9 (-33.1118, 47.0059) -> (-33.1118, 45.5559)
  line L10 (-39.6118, 47.0059) -> (-33.1118, 47.0059)
  line L11 (-39.6118, 39.6118) -> (-39.6118, 47.0059)
  line L12 (-22.1725, 22.1725) -> (-39.6118, 39.6118)
  arc A1 centre (-21.1118, 23.2332) radius 1.5 clockwise from (-19.6118, 23.2332) to (-22.1725, 22.1725)
  circle C1 centre (-28.6118, 49.8059) radius 0.85
  point P16 (-28.6118, 49.8059)
  midpoint L7 P16
  dimension "d244" diameter C1 = 1.7 (= "filament_hole_width")
sketch "Sketch9" plane through (50, 0, 0) normal (1, 0, 0) x axis (0, 1, 0)
  line L1 (49.1118, 47.0059) -> (55.6118, 47.0059)
  line L2 (49.1118, 45.5559) -> (49.1118, 47.0059)
  line L3 (44.6118, 45.5559) -> (49.1118, 45.5559)
  line L4 (44.6118, 54.0559) -> (44.6118, 45.5559)
  line L5 (49.1118, 54.0559) -> (44.6118, 54.0559)
  line L6 (49.1118, 52.6059) -> (49.1118, 54.0559)
  line L7 (55.6118, 52.6059) -> (49.1118, 52.6059)
  line L8 (55.6118, 60) -> (55.6118, 52.6059)
  line L9 (39.6118, 60) -> (55.6118, 60)
  line L10 (39.6118, 52.4859) -> (39.6118, 60)
  line L11 (32.9918, 52.4859) -> (39.6118, 52.4859)
  line L12 (32.9918, 53.9359) -> (32.9918, 52.4859)
  line L13 (28.7318, 53.9359) -> (32.9918, 53.9359)
  line L14 (28.7318, 45.6759) -> (28.7318, 53.9359)
  line L15 (32.9918, 45.6759) -> (28.7318, 45.6759)
  line L16 (32.9918, 47.1259) -> (32.9918, 45.6759)
  line L17 (39.6118, 47.1259) -> (32.9918, 47.1259)
  line L18 (39.6118, 10) -> (39.6118, 47.1259)
  line L19 (55.6118, 10) -> (39.6118, 10)
  line L20 (55.6118, 47.0059) -> (55.6118, 10)
  circle C1 centre (28.7318, 49.8059) radius 0.85
  circle C2 centre (44.6118, 49.8059) radius 0.85
  point P22 (28.7318, 49.8059)
  point P23 (44.6118, 49.8059)
  midpoint L14 P22
  midpoint L4 P23
  dimension "d247" diameter C1 = 1.7 (= "filament_hole_width")
  dimension "d250" diameter C2 = 1.7 (= "filament_hole_width")
extrude "Extrude12" cut sketch "Sketch9" profile of L4 L14 C1 C2 no distance stored
sketch "Sketch16" plane through (0, 19.6118, 0) normal (0, -1, 0) x axis (1, 0, 0)
  line L1 (0, 60) -> (40, 60)
  line L2 (40, 23.2332) -> (0, 23.2332)
  curve K1
  curve K2
  curve K3
  curve K4
  line L3 (40, 60) -> (40, 23.2332)
  line L4 (0, 23.2332) -> (0, 60)
  line L5 (14.0949, 43.2512) -> (13.8576, 43.2561)
  line L6 (14.0327, 40.2395) -> (14.0949, 43.2512)
  line L7 (13.6644, 40.2471) -> (14.0327, 40.2395)
  line L8 (13.7129, 42.5938) -> (13.6644, 40.2471)
  curve K5 (13.3578, 42.3474) -> (13.7129, 42.5938)
  curve K6 (12.9672, 42.1651) -> (13.3578, 42.3474)
  line L9 (12.9745, 42.5211) -> (12.9672, 42.1651)
  curve K7 (13.5219, 42.8618) -> (12.9745, 42.5211)
  curve K8 (13.8576, 43.2561) -> (13.5219, 42.8618)
  line L10 (17.2592, 40.1729) -> (17.7336, 41.8353)
  line L11 (16.8745, 40.1808) -> (17.2592, 40.1729)
  line L12 (16.2545, 42.3674) -> (16.8745, 40.1808)
  line L13 (16.635, 42.3595) -> (16.2545, 42.3674)
  line L14 (16.9549, 41.0982) -> (16.635, 42.3595)
  line L15 (17.0741, 40.629) -> (16.9549, 41.0982)
  curve K9 (17.1959, 41.0748) -> (17.0741, 40.629)
  line L16 (17.568, 42.3402) -> (17.1959, 41.0748)
  line L17 (17.9465, 42.3324) -> (17.568, 42.3402)
  line L18 (18.2457, 41.0654) -> (17.9465, 42.3324)
  line L19 (18.3456, 40.6478) -> (18.2457, 41.0654)
  line L20 (18.4791, 41.0646) -> (18.3456, 40.6478)
  line L21 (18.8774, 42.3132) -> (18.4791, 41.0646)
  line L22 (19.2354, 42.3058) -> (18.8774, 42.3132)
  line L23 (18.5113, 40.147) -> (19.2354, 42.3058)
  line L24 (18.1287, 40.1549) -> (18.5113, 40.147)
  line L25 (17.8098, 41.4633) -> (18.1287, 40.1549)
  line L26 (17.7336, 41.8353) -> (17.8098, 41.4633)
  curve K10 (20.366, 40.3605) -> (19.9904, 40.5094)
  curve K11 (20.8203, 40.5517) -> (20.366, 40.3605)
  line L27 (16.085, 41.0977) -> (16.0926, 41.468)
  line L28 (14.9536, 41.1211) -> (16.085, 41.0977)
  line L29 (14.9612, 41.4914) -> (14.9536, 41.1211)
  line L30 (16.0926, 41.468) -> (14.9612, 41.4914)
  line L31 (11.6001, 40.2898) -> (12.4674, 42.4456)
  line L32 (11.2563, 40.2969) -> (11.6001, 40.2898)
  line L33 (10.4747, 42.4867) -> (11.2563, 40.2969)
  line L34 (10.8634, 42.4787) -> (10.4747, 42.4867)
  line L35 (11.303, 41.1679) -> (10.8634, 42.4787)
  curve K12 (11.4331, 40.7271) -> (11.303, 41.1679)
  curve K13 (11.5787, 41.1376) -> (11.4331, 40.7271)
  line L36 (12.0889, 42.4534) -> (11.5787, 41.1376)
  line L37 (12.4674, 42.4456) -> (12.0889, 42.4534)
  curve K14 (20.494, 42.0956) -> (19.9234, 41.919)
  curve K15 (19.9904, 40.5094) -> (19.8008, 40.9391)
  curve K16 (21.0154, 41.0798) -> (20.8203, 40.5517)
  curve K17 (20.8477, 41.5806) -> (21.0154, 41.0798)
  curve K18 (20.389, 41.7723) -> (20.8477, 41.5806)
  curve K19 (20.0661, 41.6971) -> (20.389, 41.7723)
  curve K20 (19.8368, 41.493) -> (20.0661, 41.6971)
  curve K21 (21.4068, 41.1045) -> (21.1512, 41.8098)
  curve K22 (21.155, 40.4056) -> (21.4068, 41.1045)
  line L38 (19.8008, 40.9391) -> (19.4134, 40.9144)
  curve K23 (21.1512, 41.8098) -> (20.494, 42.0956)
  curve K24 (19.6955, 40.3006) -> (20.3598, 40.0577)
  curve K25 (19.4134, 40.9144) -> (19.6955, 40.3006)
  line L39 (19.4919, 41.5452) -> (19.8368, 41.493)
  line L40 (19.8143, 43.0798) -> (19.4919, 41.5452)
  line L41 (21.3058, 43.049) -> (19.8143, 43.0798)
  line L42 (21.2985, 42.6971) -> (21.3058, 43.049)
  line L43 (20.1016, 42.7218) -> (21.2985, 42.6971)
  line L44 (19.9234, 41.919) -> (20.1016, 42.7218)
  curve K26 (20.3598, 40.0577) -> (21.155, 40.4056)
  curve K27 (29.014, 42.8447) -> (28.5925, 42.9517)
  curve K28 (29.309, 42.5582) -> (29.014, 42.8447)
  curve K29 (27.709, 42.2924) -> (27.5829, 41.4395)
  curve K30 (28.0446, 42.787) -> (27.709, 42.2924)
  curve K31 (28.5925, 42.9517) -> (28.0446, 42.787)
  curve K32 (29.4859, 42.1084) -> (29.309, 42.5582)
  curve K33 (26.9786, 42.6064) -> (26.6837, 42.8929)
  curve K34 (27.1556, 42.1565) -> (26.9786, 42.6064)
  curve K35 (25.3787, 42.3406) -> (25.2525, 41.4876)
  curve K36 (25.7143, 42.8351) -> (25.3787, 42.3406)
  curve K37 (26.2622, 42.9998) -> (25.7143, 42.8351)
  curve K38 (26.6837, 42.8929) -> (26.2622, 42.9998)
  curve K39 (27.8544, 40.214) -> (28.5292, 39.8889)
  curve K40 (27.5829, 41.4395) -> (27.8544, 40.214)
  curve K41 (29.5388, 41.3991) -> (29.4859, 42.1084)
  curve K42 (29.4128, 40.5481) -> (29.5388, 41.3991)
  curve K43 (29.0771, 40.0536) -> (29.4128, 40.5481)
  curve K44 (28.5292, 39.8889) -> (29.0771, 40.0536)
  curve K45 (22.0295, 40.3343) -> (22.7044, 40.0092)
  curve K46 (21.7581, 41.5598) -> (22.0295, 40.3343)
  curve K47 (21.8842, 42.4128) -> (21.7581, 41.5598)
  curve K48 (22.2198, 42.9073) -> (21.8842, 42.4128)
  curve K49 (22.7677, 43.072) -> (22.2198, 42.9073)
  curve K50 (23.1892, 42.9651) -> (22.7677, 43.072)
  curve K51 (23.4841, 42.6785) -> (23.1892, 42.9651)
  curve K52 (23.6611, 42.2287) -> (23.4841, 42.6785)
  curve K53 (23.714, 41.5194) -> (23.6611, 42.2287)
  curve K54 (23.5879, 40.6685) -> (23.714, 41.5194)
  curve K55 (23.2523, 40.1739) -> (23.5879, 40.6685)
  curve K56 (22.7044, 40.0092) -> (23.2523, 40.1739)
  curve K57 (25.524, 40.2621) -> (26.1989, 39.937)
  curve K58 (25.2525, 41.4876) -> (25.524, 40.2621)
  curve K59 (27.2085, 41.4472) -> (27.1556, 42.1565)
  curve K60 (27.0824, 40.5963) -> (27.2085, 41.4472)
  curve K61 (26.7468, 40.1017) -> (27.0824, 40.5963)
  curve K62 (26.1989, 39.937) -> (26.7468, 40.1017)
  line L45 (24.6839, 40.0195) -> (24.6926, 40.4389)
  line L46 (24.2645, 40.0282) -> (24.6839, 40.0195)
  line L47 (24.2732, 40.4476) -> (24.2645, 40.0282)
  line L48 (24.6926, 40.4389) -> (24.2732, 40.4476)
  circle C1 centre (20, 49.8059) radius 1.06
  point P2 (40, 23.2332)
  point P4 (0, 60)
  coincident P2
  coincident P4
  dimension "d253" Text1-Height = 3
extrude "Extrude22" cut sketch "Sketch16" against normal blind 2
extrude "Extrude23" cut sketch "Sketch15" profile of L7 C1 against normal blind 2000
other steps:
create_component "CreateComponent1"
create_component "CreateComponent2"
create_component "CreateComponent3"
create_component "CreateComponent4"
named bodies: "Wall anchor part", "Base plate with slot"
